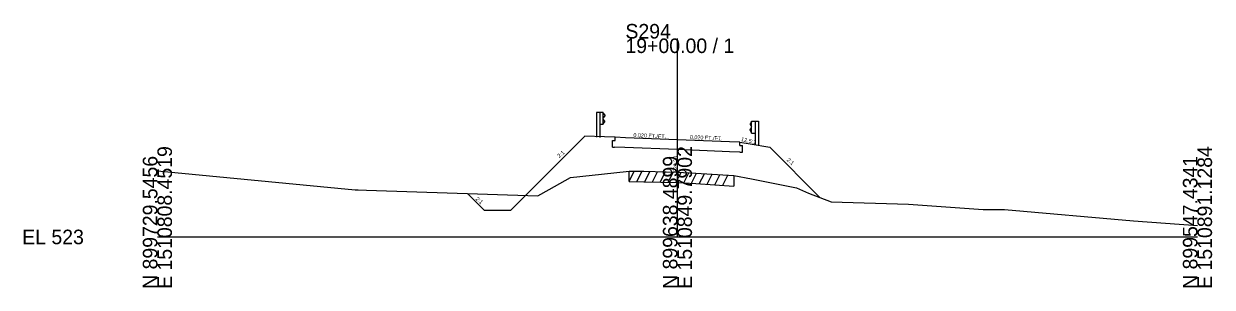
# Model space of a CAD drawing. Extents: x 974 to 2203, y -10 to 19041.
# Drawn here: x 974.3 to 1202.8, y 17990.3 to 18041.1 of the extents above; entities that cross this region are included whole.
import ezdxf

# ---------------------------------------------------------------- set-up
doc = ezdxf.new("R2010")
doc.units = 0
for name, color, linetype in [('RD_GPK_XS_Cell', 7, 'Continuous'), ('RD_XS_Base', 7, 'Continuous'), ('RD_XS_EarthShd', 7, 'Continuous'), ('RD_XS_ExGround', 7, 'Continuous'), ('RD_XS_ExPaveRet', 7, 'Continuous'), ('RD_XS_GR', 7, 'Continuous'), ('RD_XS_Pave', 7, 'Continuous'), ('RD_XS_TX_Elev_EX', 7, 'Continuous'), ('RD_XS_TX_Slope', 7, 'Continuous')]:
    doc.layers.add(name, color=color, linetype=linetype)

msp = doc.modelspace()

# ---------------------------------------------------------------- linework, layer by layer
at = {"layer": 'RD_GPK_XS_Cell'}
for p, q in [((1100, 18000), (1100, 18038.22)), ((1000, 18000), (1100, 18000)), ((1100, 18000), (1200, 18000))]:
    msp.add_line(p, q, dxfattribs=at)
at = {"layer": 'RD_XS_Base'}
for p, q in [((1087.5, 18017.31), (1087.5, 18018.58)), ((1087.5, 18018.58), (1088, 18018.56)), ((1088, 18018.56), (1088, 18019.2)), ((1112, 18017.6), (1112, 18018.24)), ((1112, 18017.6), (1112.5, 18017.58)), ((1112.5, 18016.31), (1112.5, 18017.58)), ((1087.5, 18017.31), (1087.89, 18017.3)), ((1089.89, 18017.22), (1087.89, 18017.3)), ((1099.95, 18016.82), (1089.89, 18017.22)), ((1110, 18016.41), (1099.95, 18016.82)), ((1112, 18016.33), (1110, 18016.41)), ((1112, 18016.33), (1112.5, 18016.31))]:
    msp.add_line(p, q, dxfattribs=at)
at = {"layer": 'RD_XS_EarthShd'}
for p, q in [((1067.89, 18005.12), (1082.2, 18019.43)), ((1086, 18019.28), (1082.2, 18019.43)), ((1088, 18019.2), (1086, 18019.28)), ((1112, 18018.24), (1114, 18017.91)), ((1114, 18017.91), (1117.75, 18017.28)), ((1127.48, 18007.55), (1117.75, 18017.28)), ((1062.89, 18005.12), (1059.64, 18008.36)), ((1067.89, 18005.12), (1062.89, 18005.12))]:
    msp.add_line(p, q, dxfattribs=at)
at = {"layer": 'RD_XS_ExGround'}
msp.add_lwpolyline([(1000, 18012.74), (1038.03, 18009.08), (1038.63, 18009.05), (1040.19, 18008.99), (1073.17, 18007.93), (1075.32, 18009.14), (1079.43, 18011.45), (1087.79, 18012.33), (1090.71, 18012.68), (1093.53, 18012.64), (1100, 18012.46), (1101.16, 18012.43), (1103.52, 18012.28), (1110.86, 18011.81), (1114.22, 18011.2), (1122.88, 18009.47), (1125.2, 18008.45), (1129.55, 18006.74), (1144.43, 18006.3), (1158.78, 18005.31), (1162.89, 18005.26), (1187.72, 18003.12), (1200, 18002.21)], dxfattribs=at)
at = {"layer": 'RD_XS_ExPaveRet'}
for p, q in [((1090.71, 18010.68), (1090.71, 18012.68)), ((1090.71, 18010.68), (1091.71, 18012.67)), ((1090.71, 18010.68), (1093.53, 18010.64)), ((1092.21, 18010.66), (1093.21, 18012.64)), ((1093.71, 18010.63), (1094.7, 18012.6)), ((1095.21, 18010.59), (1096.2, 18012.56)), ((1096.71, 18010.55), (1097.7, 18012.52)), ((1098.21, 18010.51), (1099.2, 18012.48)), ((1099.71, 18010.47), (1100.7, 18012.44)), ((1101.21, 18010.43), (1102.18, 18012.37)), ((1102.71, 18010.33), (1103.68, 18012.27)), ((1104.21, 18010.24), (1105.18, 18012.18)), ((1105.71, 18010.14), (1106.68, 18012.08)), ((1107.21, 18010.05), (1108.18, 18011.98)), ((1108.71, 18009.95), (1109.68, 18011.89)), ((1110.86, 18011.81), (1110.86, 18009.81)), ((1093.53, 18010.64), (1100, 18010.46)), ((1100, 18010.46), (1101.16, 18010.43)), ((1101.16, 18010.43), (1103.52, 18010.28)), ((1103.52, 18010.28), (1110.86, 18009.81))]:
    msp.add_line(p, q, dxfattribs=at)
at = {"layer": 'RD_XS_GR'}
for p, q in [((1084.41, 18023.97), (1084.41, 18019.21)), ((1085.08, 18023.97), (1084.41, 18023.97)), ((1085.08, 18023.97), (1085.08, 18019.18)), ((1085.74, 18023.97), (1085.08, 18023.97)), ((1085.74, 18021.64), (1085.74, 18023.97)), ((1085.74, 18023.83), (1086.01, 18023.43)), ((1086.01, 18023.33), (1085.74, 18022.93)), ((1086.01, 18022.29), (1085.74, 18022.69)), ((1085.74, 18021.79), (1086.01, 18022.19)), ((1086.01, 18023.43), (1086.01, 18023.33)), ((1086.01, 18022.19), (1086.01, 18022.29)), ((1114.27, 18022.18), (1114, 18021.78)), ((1114.27, 18022.32), (1114.94, 18022.32)), ((1114.27, 18019.99), (1114.27, 18022.32)), ((1114.94, 18022.32), (1114.94, 18017.67)), ((1114.94, 18022.32), (1115.6, 18022.32)), ((1115.6, 18022.32), (1115.6, 18017.56)), ((1085.74, 18021.64), (1085.08, 18021.64)), ((1114, 18021.78), (1114, 18021.68)), ((1114, 18021.68), (1114.27, 18021.28)), ((1114, 18020.64), (1114.27, 18021.04)), ((1114, 18020.54), (1114, 18020.64)), ((1114.27, 18020.14), (1114, 18020.54)), ((1114.27, 18019.99), (1114.94, 18019.99))]:
    msp.add_line(p, q, dxfattribs=at)
at = {"layer": 'RD_XS_Pave'}
for p, q in [((1090, 18019.12), (1088, 18019.2)), ((1100, 18018.72), (1090, 18019.12)), ((1110, 18018.32), (1100, 18018.72)), ((1112, 18018.24), (1110, 18018.32))]:
    msp.add_line(p, q, dxfattribs=at)

# ---------------------------------------------------------------- texts
at = {"layer": 'RD_GPK_XS_Cell'}
for s, p in [('S294', (1090, 18038.22)), ('19+00.00 / 1', (1090, 18035.42)), ('EL 523', (974, 17998.6))]:
    msp.add_text(s, height=2.8, dxfattribs=at).set_placement(p)
for s, p in [('N 899729.5456', (1000, 17990)), ('E 1510808.4519', (1002.8, 17990)), ('N 899638.4899', (1100, 17990)), ('E 1510849.7902', (1102.8, 17990)), ('N 899547.4341', (1200, 17990)), ('E 1510891.1284', (1202.8, 17990))]:
    msp.add_text(s, height=2.8, rotation=90, dxfattribs=at).set_placement(p)
at = {"layer": 'RD_XS_TX_Elev_EX'}
msp.add_text('529.23', height=0.75, rotation=90, dxfattribs=at).set_placement((1100, 18012.46))
at = {"layer": 'RD_XS_TX_Slope'}
for s, height, rotation, p in [('0.020 FT./FT.', 0.7518, 357.7673, (1091.53, 18019.25)), ('0.020 FT./FT.', 0.7518, 357.7673, (1102.39, 18018.86)), ('12.5:1', 0.778, 347.2489, (1112.17, 18018.49)), ('2:1', 0.778, 40.6589, (1077.26, 18015.17)), ('2:1', 0.778, 319.3411, (1120.92, 18014.74)), ('2:1', 0.778, 319.3411, (1061.09, 18007.22))]:
    msp.add_text(s, height=height, rotation=rotation, dxfattribs=at).set_placement(p)

doc.saveas('drawing.dxf')
